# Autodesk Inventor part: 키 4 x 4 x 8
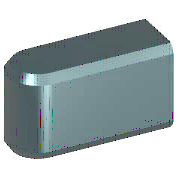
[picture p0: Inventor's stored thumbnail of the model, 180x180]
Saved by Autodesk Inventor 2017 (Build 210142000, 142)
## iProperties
Created: 2012-02
Part Number: 키 4 x 4 x 8
Material: 강철, 연강
Description: 키 및 해당 키홈
Document SubType Name: Modeling
Standard: KS B 1311
Designer: mduedu
Standards Organization: KS
Language: ko-KR
Size Designation: 4 x 4 x 8
Categories: <MemberInstance><Categories><Category DisplayName="샤프트 부품" InternalName="7f7aeb1f-a693-4053-b835-cee3144e0d98" Mnemonic="SHFT"><Category DisplayName="키" Interna
Density: 1 g/cm^3
Appearance: 노란색
IsCustomPart: 1
Author: mduedu
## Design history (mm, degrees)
sketch "스케치1"
  geometry: L1 (2, 2)-(8, 2); L2 (8, 2)-(8, -2); L3 (8, -2)-(2, -2); L4 (0, 7)-(0, -7) reference; L5 (-5, 0)-(30, 0) reference; A1 r 2 centre (2, 0) between (2, 2) and (2, -2)
  constraints: 6 end point, 3 tangent, 2 point on circle, 1 centre point, 1 horizontal, 1 parallel, 1 perpendicular, 1 point on line
  dimensions: "d0" = 2 radius of A1 (= 0.5 x PB); "d7" = 8 distance between parallel lines of L2 L4 (= NLG)
workplane "Work Plane1"
workplane "Work Plane2"
extrude "본체1" new body sketch "스케치1" taper "d3" = 0 deg; stored distance "d4" = 10
workaxis "Work Axis1"
workplane "Work Plane4"
body "Solid1"
chamfer "모따기1" distance "d8" = 0.25 (= PHH); stored, may be unused: second distance "d9" = 0.25 (= PHH), angle "d13" = 45 deg
other parameters: "d1" = -2.5 (= -PNT), "d2" = 1.5 (= PH - PNT), "NLG" = 8 [user parameter; used in 2 equation terms], "PB" = 4 [user parameter; used in 1 equation term], "PNT" = 2.5 [user parameter; used in 2 equation terms], "PH" = 4 [user parameter; used in 1 equation term], "PHH" = 0.25 [user parameter; used in 2 equation terms], "d10" = 0, "d16" = 0, "d17" = 0, "d18" = 0, "RR" = 0.08 [user parameter], "WDMAX" = 12 [user parameter], "PLB1" = 8 (= NLG) [user parameter], "PUEB" = 1.8 [user parameter]
